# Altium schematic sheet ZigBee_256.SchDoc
size A3
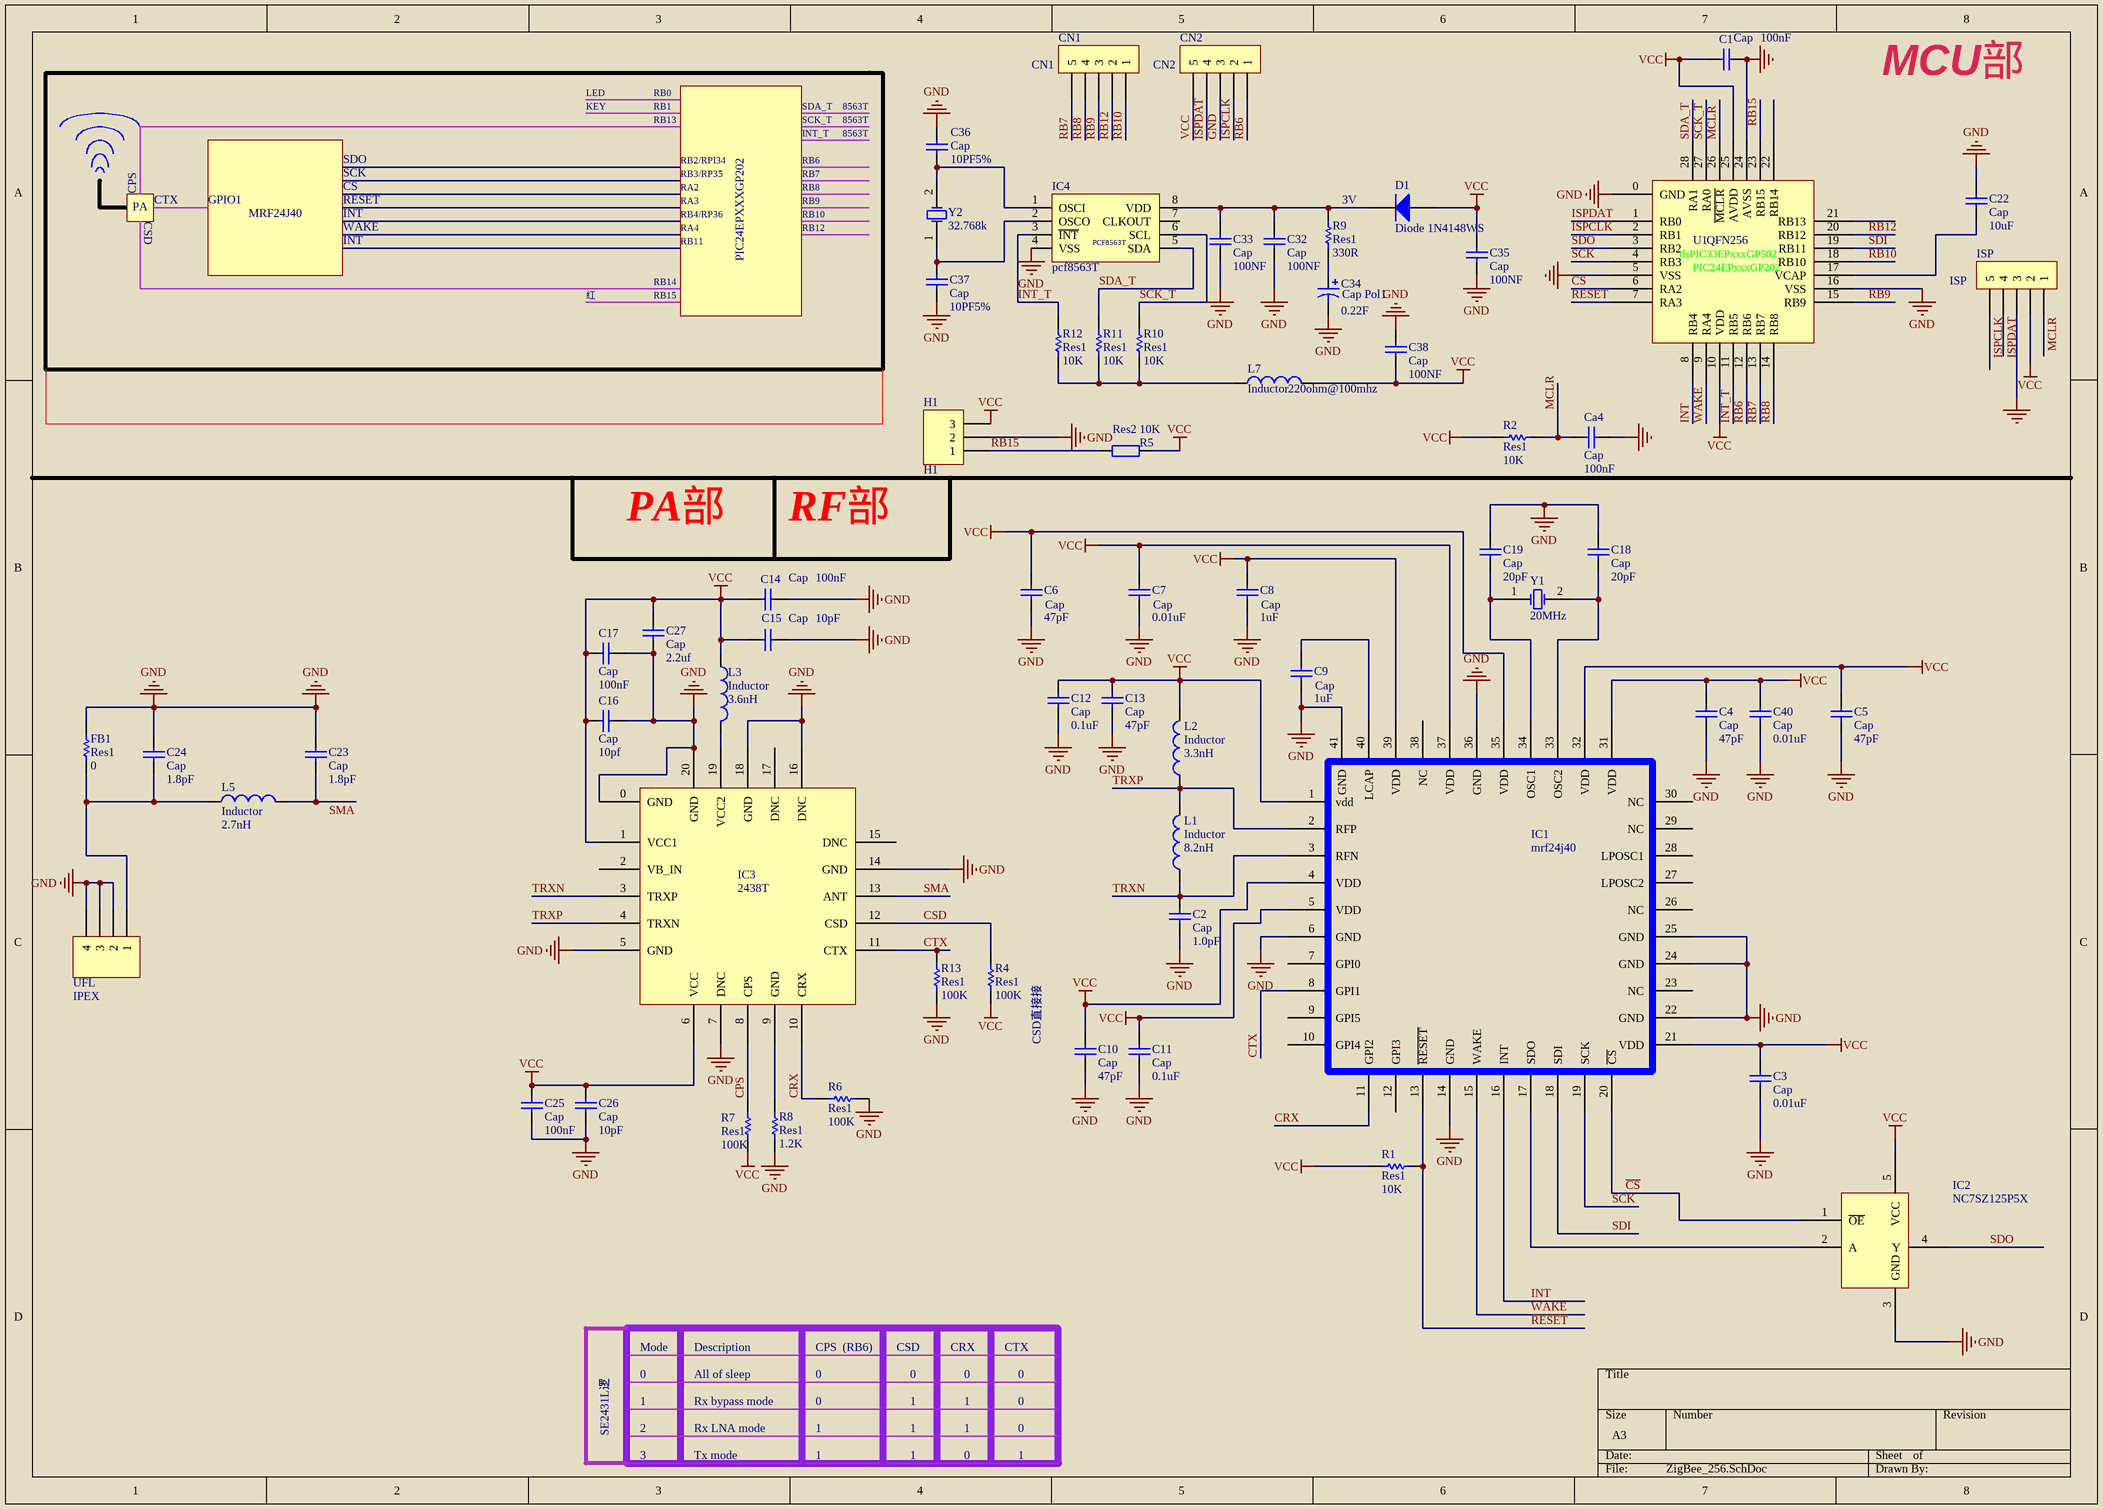
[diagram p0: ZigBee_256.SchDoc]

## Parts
C1  Cap  value 100nF  [C0402]
C2  Cap  value 1.0pF  [C0402]
C3  Cap  value 0.01uF  [C0402]
C4  Cap  value 47pF  [C0402]
C5  Cap  value 47pF  [C0402]
C6  Cap  value 47pF  [C0402]
C7  Cap  value 0.01uF  [C0402]
C8  Cap  value 1uF  [C0402]
C9  Cap  value 1uF  [C0402]
C10  Cap  value 47pF  [C0402]
C11  Cap  value 0.1uF  [C0402]
C12  Cap  value 0.1uF  [C0402]
C13  Cap  value 47pF  [C0402]
C14  Cap  value 100nF  [C0402]
C15  Cap  value 10pF  [C0402]
C16  Cap  value 10pf  [C0402]
C17  Cap  value 100nF  [C0402]
C18  Cap  value 20pF  [C0402]
C19  Cap  value 20pF  [C0402]
C22  Cap  value 10uF  [C0402]
C23  Cap  value 1.8pF  [C0402]
C24  Cap  value 1.8pF  [C0402]
C25  Cap  value 100nF  [C0402]
C26  Cap  value 10pF  [C0402]
C27  Cap  value 2.2uf  [C0402]
C32  Cap  value 100NF  [C0402]
C33  Cap  value 100NF  [C0402]
C34  Cap Pol1  value 0.22F  [0.22f]
C35  Cap  value 100NF  [C0402]
C36  Cap  value 10PF5%  [C0402]
C37  Cap  value 10PF5%  [C0402]
C38  Cap  value 100NF  [C0402]
C40  Cap  value 0.01uF  [C0402]
Ca4  Cap  value 100nF  [C0402]
CN1  CN1  [SIP5]
CN2  CN2  [SIP5]
D1  Diode 1N4148WS  [sod323]
FB1  Res1  value 0  [C0402]
H1  H1  [HDR1X3]
IC1  mrf24j40  [mrf24j40]
IC2  NC7SZ125P5X  [NC7SZ125P5X]
IC3  2438T  [2438T]
IC4  pcf8563T  [pcf8563t]
ISP  ISP  [1.27MM]
L1  Inductor  value 8.2nH  [c0402]
L2  Inductor  value 3.3nH  [c0402]
L3  Inductor  value 3.6nH  [c0402]
L5  Inductor  value 2.7nH  [c0402]
L7  Inductor  value 220ohm@100mhz  [c0402]
R1  Res1  value 10K  [C0402]
R2  Res1  value 10K  [C0402]
R4  Res1  value 100K  [C0402]
R5  Res2  value 10K  [C0402]
R6  Res1  value 100K  [C0402]
R7  Res1  value 100K  [C0402]
R8  Res1  value 1.2K  [C0402]
R9  Res1  value 330R  [C0402]
R10  Res1  value 10K  [C0402]
R11  Res1  value 10K  [C0402]
R12  Res1  value 10K  [C0402]
R13  Res1  value 100K  [C0402]
U1  QFN256  [QFN256]
UFL  IPEX  [UFL]
Y1  20MHz  [20mhz]
Y2  32.768k  [32.768K]

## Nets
GND: C1.2 C2.1 C3.1 C4.1 C5.1 C6.1 C7.1 C8.1 C9.1 C10.1 C11.1 C12.1 C13.1 C14.1 C15.1 C16.1 C17.2 C18.2 C19.2 C22.1 C23.1 C24.1 C25.1 C26.1 C27.1 C32.2 C33.2 C34.2 C35.2 C36.1 C37.1 C38.2 C40.1 Ca4.1 CN2.3 FB1.1 H1.2 IC1.6(GND) IC1.14(GND) IC1.22(GND) IC1.24(GND) IC1.25(GND) IC1.36(GND) IC1.41(GND) IC2.3(GND) IC3.0(GND) IC3.5(GND) IC3.7(DNC) IC3.14(GND) IC3.16(DNC) IC3.18(GND) IC3.20(GND) IC4.4(VSS) ISP.3 R6.2 R8.2 R13.1 U1.0(GND) U1.5(VSS) U1.16(VSS) U1.24(AVSS) UFL.2 UFL.3 UFL.4
VCC: C1.1 C3.2 C4.2 C5.2 C6.2 C7.2 C8.2 C10.2 C11.2 C12.2 C13.2 C14.2 C15.2 C16.2 C17.1 C25.2 C26.2 C27.2 C35.1 C38.1 C40.2 CN2.5 D1.1(A) H1.3 IC1.1(vdd) IC1.4(VDD) IC1.5(VDD) IC1.21(VDD) IC1.31(VDD) IC1.32(VDD) IC1.35(VDD) IC1.37(VDD) IC1.39(VDD) IC2.5(VCC) IC3.1(VCC1) IC3.6(VCC) ISP.2 L2.2 L3.1 L7.2 R1.1 R2.2 R4.1 R5.2 R7.2 U1.10(VDD) U1.25(AVDD)
~{CS}: IC1.20(~{CS}) IC2.1(~{OE}) U1.6(RA2)
CPS: IC3.8(CPS) R7.1
CRX: IC1.11(GPI2) IC3.10(CRX) R6.1
CSD: IC3.12(CSD) R4.2
CTX: IC1.8(GPI1) IC3.11(CTX) R13.2
INT: IC1.16(INT) U1.8(RB4)
INT_T: IC4.3(~{INT}) R12.1 U1.11(RB5)
ISPCLK: CN2.2 ISP.5 U1.2(RB1)
ISPDAT: CN2.4 ISP.4 U1.1(RB0)
MCLR: Ca4.2 ISP.1 R2.1 U1.26(~{MCLR})
~{RESET}: IC1.13(~{RESET}) R1.2 U1.7(RA3)
RB6: CN2.1 U1.12(RB6)
RB7: CN1.5 U1.13(RB7)
RB8: CN1.4 U1.14(RB8)
RB9: CN1.3 U1.15(RB9)
RB10: CN1.1 U1.18(RB10)
RB12: CN1.2 U1.20(RB12)
RB15: H1.1 R5.1 U1.23(RB15)
SCK: IC1.19(SCK) U1.4(RB3)
SCK_T: IC4.6(SCL) R10.1 U1.27(RA0)
SDA_T: IC4.5(SDA) R11.1 U1.28(RA1)
SDI: IC1.18(SDI) U1.19(RB11)
SDO: IC2.4(Y) U1.3(RB2)
SMA: C23.2 IC3.13(ANT) L5.2
TRXN: C2.2 IC1.3(RFN) IC3.3(TRXP) L1.1
TRXP: IC1.2(RFP) IC3.4(TRXN) L1.2 L2.1
WAKE: IC1.15(WAKE) U1.9(RA4)
NetC9_2: C9.2 IC1.40(LCAP)
NetC18_1: C18.1 IC1.33(OSC2) Y1.2(OSC2)
NetC19_1: C19.1 IC1.34(OSC1) Y1.1(OSC1)
NetC22_2: C22.2 U1.17(VCAP)
NetC24_2: C24.2 FB1.2 L5.1 UFL.1
NetC32_1: C32.1 C33.1 D1.2(K) IC4.8(VDD) R9.1
NetC34_1: C34.1 R9.2
NetC36_2: C36.2 IC4.1(OSCI) Y2.2(OSC2)
NetC37_2: C37.2 IC4.2(OSCO) Y2.1(OSC1)
NetIC1_17: IC1.17(SDO) IC2.2(A)
NetIC3_9: IC3.9(GND) R8.1
NetIC3_19: IC3.19(VCC2) L3.2
NetL7_1: L7.1 R10.2 R11.2 R12.2

Not connected (* = marked no-connect by the designer): IC1 7(GPI0) 9(GPI5) 10(GPI4) 12(GPI3) 23(NC) 26(NC) 27(LPOSC2) 28(LPOSC1) 29(NC) 30(NC) 38(NC); IC3 2(VB_IN) 15(DNC) 17(DNC); IC4 7(CLKOUT); U1 21(RB13) 22(RB14)

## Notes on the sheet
- LED
- KEY
- RB0
- RB1
- SDA_T
- 8563T
- SDO
- SCK
- RB13
- RB2/RPI34
- RB3/RP35
- RB6
- RB7
- SCK_T
- INT_T
- PA
- CPS
- CSD
- CTX
- GPIO1
- MRF24J40
- CS
- INT
- RESET
- WAKE
- RA2
- RA3
- RB4/RP36
- RA4
- RB11
- RB8
- RB9
- RB10
- RB12
- (near R9) 3V
- 红
- RB14
- RB15
- PIC24EPXXXGP202
- CSD直接接
- Mode
- 0
- Description
- All of sleep
- (RB6)
- CRX
- SE2431L逻
- 1
- 2
- 3
- Rx bypass mode
- Rx LNA mode
- Tx mode
- Labels drawn without touching a wire or pin: MCU部, PA部, RF部

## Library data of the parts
C1-C19 C22-C27 C32 C33 C35-C38 C40 Ca4 = Cap: Capacitor
C34 = Cap Pol1: Polarized Capacitor (Radial)
CN1 CN2 ISP = CON5: Connector
D1 = Diode 1N4148: High Conductance Fast Diode
FB1 R1 R2 R4 R6-R13 = Res1: Resistor
H1 = Header 3: Header, 3-Pin
L1-L3 L5 L7 = Inductor: Code_IEC: 1005
R5 = Res2: Resistor
UFL = Header 4: Header, 4-Pin
Y1 Y2 = XTAL: Crystal Oscillator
